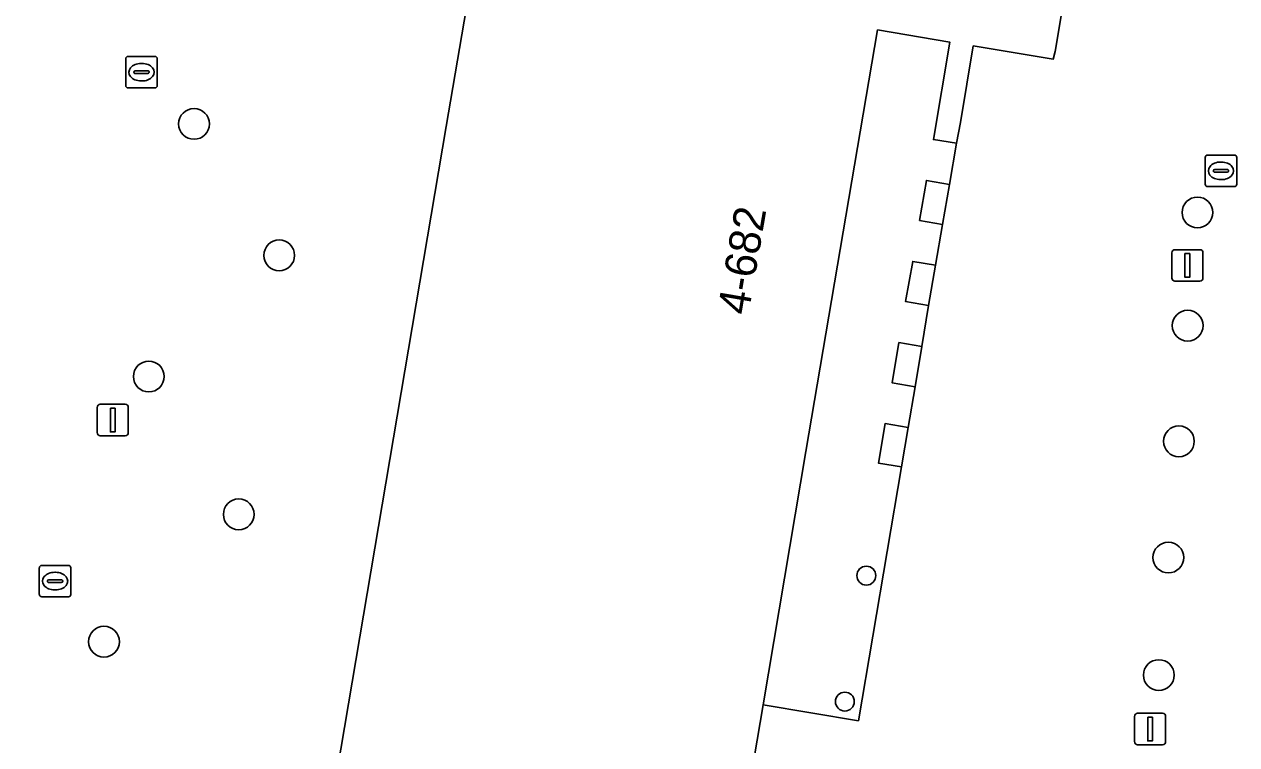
# Model space of a CAD drawing. Extents: x 161258 to 161838, y 380833 to 381727.
# Drawn here: x 161411.27 to 161449.78, y 380983.15 to 381006.05 of the extents above; entities that cross this region are included whole.
import ezdxf

# ---------------------------------------------------------------- set-up
doc = ezdxf.new("R2010")
doc.units = 0
for name, color, linetype in [('IMGEO_Boom', 7, 'Continuous'), ('IMGEO_Erf', 7, 'Continuous'), ('IMGEO_Kolk', 7, 'Continuous'), ('IMGEO_Lichtmast', 7, 'Continuous'), ('IMGEO_Pand', 7, 'Continuous'), ('IMGEO_Pand_nummerreeks', 7, 'Continuous'), ('IMGEO_Pand_overbouw', 7, 'Continuous')]:
    doc.layers.add(name, color=color, linetype=linetype)

msp = doc.modelspace()

# ---------------------------------------------------------------- linework, layer by layer
at = {"layer": 'IMGEO_Boom'}
for centre in [(161416.661, 381002.88), (161448.534, 381000.066), (161419.366, 380998.703), (161448.225, 380996.469), (161415.223, 380994.852), (161447.945, 380992.793), (161418.081, 380990.471), (161447.611, 380989.099), (161413.8, 380986.425), (161447.307, 380985.364)]:
    msp.add_circle(centre, 0.489, dxfattribs=at)
at = {"layer": 'IMGEO_Erf'}
msp.add_lwpolyline([(161408.328, 380973.621), (161419.413, 380971.739), (161420.011, 380975.246), (161424.673, 381002.799), (161429.081, 381028.658), (161440.253, 381026.759), (161437.41, 381010.081), (161444.625, 381008.855), (161444.015, 381005.179), (161443.954, 381004.94), (161441.41, 381005.361), (161441.008, 381002.927), (161440.881, 381002.266), (161440.145, 381002.382), (161440.67, 381005.478), (161438.373, 381005.868), (161436.092, 380992.474), (161434.734, 380984.423), (161433.514, 380977.179), (161432.521, 380971.424), (161434.023, 380971.148), (161434.118, 380956.967)], dxfattribs=at)
for points in [[(161440.436, 380999.688), (161439.709, 380999.812), (161439.925, 381001.083), (161440.659, 381000.958)], [(161439.994, 380997.106), (161439.265, 380997.233), (161439.488, 380998.512), (161440.217, 380998.388)], [(161439.567, 380994.528), (161438.833, 380994.656), (161439.049, 380995.929), (161439.776, 380995.805)], [(161439.133, 380991.981), (161438.399, 380992.102), (161438.612, 380993.356), (161439.341, 380993.233)]]:
    msp.add_lwpolyline(points, close=True, dxfattribs=at)
for centre, start, end in [((161438.016, 380988.524), 90, 270), ((161438.016, 380988.524), 270, 90), ((161437.334, 380984.521), 90, 270), ((161437.334, 380984.521), 270, 90)]:
    msp.add_arc(centre, 0.3, start, end, dxfattribs=at)
at = {"layer": 'IMGEO_Kolk'}
for p, q in [((161414.492, 381004.098), (161414.492, 381004.95)), ((161414.567, 381005.024), (161415.419, 381005.024)), ((161415.493, 381004.95), (161415.493, 381004.098)), ((161414.751, 381004.518), (161414.751, 381004.53)), ((161414.794, 381004.567), (161415.192, 381004.567)), ((161414.98, 381004.804), (161415.005, 381004.804)), ((161415.235, 381004.53), (161415.235, 381004.518)), ((161415.189, 381004.481), (161414.791, 381004.481)), ((161415.003, 381004.244), (161414.978, 381004.244)), ((161415.419, 381004.024), (161414.567, 381004.024)), ((161448.781, 381000.963), (161448.781, 381001.815)), ((161448.856, 381001.889), (161449.708, 381001.889)), ((161449.782, 381001.815), (161449.782, 381000.963)), ((161449.083, 381001.432), (161449.481, 381001.432)), ((161449.269, 381001.669), (161449.294, 381001.669)), ((161449.04, 381001.383), (161449.04, 381001.395)), ((161449.478, 381001.346), (161449.08, 381001.346)), ((161449.292, 381001.109), (161449.267, 381001.109)), ((161449.524, 381001.395), (161449.524, 381001.383)), ((161449.708, 381000.889), (161448.856, 381000.889)), ((161411.746, 380987.925), (161411.746, 380988.777)), ((161411.821, 380988.851), (161412.673, 380988.851)), ((161412.747, 380988.777), (161412.747, 380987.925)), ((161412.005, 380988.345), (161412.005, 380988.357)), ((161412.048, 380988.394), (161412.446, 380988.394)), ((161412.234, 380988.631), (161412.259, 380988.631)), ((161412.489, 380988.357), (161412.489, 380988.345)), ((161412.443, 380988.308), (161412.045, 380988.308)), ((161412.257, 380988.071), (161412.232, 380988.071)), ((161412.673, 380987.851), (161411.821, 380987.851))]:
    msp.add_line(p, q, dxfattribs=at)
for points in [[(161414.492, 381004.098), (161414.492, 381004.95)], [(161414.567, 381005.024), (161415.419, 381005.024)], [(161415.493, 381004.95), (161415.493, 381004.098)], [(161415.419, 381004.024), (161414.567, 381004.024)], [(161448.781, 381000.963), (161448.781, 381001.815)], [(161448.856, 381001.889), (161449.708, 381001.889)], [(161449.782, 381001.815), (161449.782, 381000.963)], [(161449.708, 381000.889), (161448.856, 381000.889)], [(161411.746, 380987.925), (161411.746, 380988.777)], [(161411.821, 380988.851), (161412.673, 380988.851)], [(161412.747, 380988.777), (161412.747, 380987.925)], [(161412.673, 380987.851), (161411.821, 380987.851)]]:
    msp.add_lwpolyline(points, dxfattribs=at)
for centre, radius, start, end in [((161414.569, 381004.948), 0.0765, 91.552, 178.448), ((161414.569, 381004.948), 0.0765, 91.552, 178.448), ((161415.417, 381004.948), 0.0765, 1.552, 88.448), ((161415.417, 381004.948), 0.0765, 1.552, 88.448), ((161414.791, 381004.527), 0.0403, 85.8775, 175.7526), ((161414.788, 381004.517), 0.0366, 178.938, 274.7102), ((161415.192, 381004.524), 0.043, 264.8664, 352.4533), ((161415.196, 381004.529), 0.0386, 1.7309, 96.639), ((161414.569, 381004.1), 0.0765, 181.552, 268.448), ((161414.569, 381004.1), 0.0765, 181.552, 268.448), ((161415.417, 381004.1), 0.0765, 271.552, 358.448), ((161415.417, 381004.1), 0.0765, 271.552, 358.448), ((161448.858, 381001.813), 0.0765, 91.552, 178.448), ((161448.858, 381001.813), 0.0765, 91.552, 178.448), ((161449.706, 381001.813), 0.0765, 1.552, 88.448), ((161449.706, 381001.813), 0.0765, 1.552, 88.448), ((161449.08, 381001.392), 0.0403, 85.8775, 175.7526), ((161449.485, 381001.394), 0.0386, 1.7309, 96.639), ((161449.077, 381001.382), 0.0366, 178.938, 274.7102), ((161449.481, 381001.389), 0.043, 264.8664, 352.4533), ((161448.858, 381000.965), 0.0765, 181.552, 268.448), ((161448.858, 381000.965), 0.0765, 181.552, 268.448), ((161449.706, 381000.965), 0.0765, 271.552, 358.448), ((161449.706, 381000.965), 0.0765, 271.552, 358.448), ((161411.823, 380988.775), 0.0765, 91.552, 178.448), ((161411.823, 380988.775), 0.0765, 91.552, 178.448), ((161412.671, 380988.775), 0.0765, 1.552, 88.448), ((161412.671, 380988.775), 0.0765, 1.552, 88.448), ((161412.045, 380988.354), 0.0403, 85.8775, 175.7526), ((161412.042, 380988.344), 0.0366, 178.938, 274.7102), ((161412.446, 380988.351), 0.043, 264.8664, 352.4533), ((161412.45, 380988.356), 0.0386, 1.7309, 96.639), ((161411.823, 380987.927), 0.0765, 181.552, 268.448), ((161411.823, 380987.927), 0.0765, 181.552, 268.448), ((161412.671, 380987.927), 0.0765, 271.552, 358.448), ((161412.671, 380987.927), 0.0765, 271.552, 358.448)]:
    msp.add_arc(centre, radius, start, end, dxfattribs=at)
for centre, major_axis, ratio, start_param, end_param in [((161414.979, 381004.524), (-0.387, 0.002), 0.722429, 4.712389, 7.853982), ((161415.004, 381004.524), (-0.39, 0.002), 0.717154, 1.570796, 4.712389), ((161449.268, 381001.389), (-0.387, 0.002), 0.722429, 4.712389, 7.853982), ((161449.293, 381001.389), (-0.39, 0.002), 0.717154, 1.570796, 4.712389), ((161412.233, 380988.351), (-0.387, 0.002), 0.722429, 4.712389, 7.853982), ((161412.258, 380988.351), (-0.39, 0.002), 0.717154, 1.570796, 4.712389)]:
    msp.add_ellipse(centre, major_axis=major_axis, ratio=ratio, start_param=start_param, end_param=end_param, dxfattribs=at)
at = {"layer": 'IMGEO_Lichtmast'}
for p, q in [((161447.718, 380997.982), (161447.718, 380998.782)), ((161447.718, 380998.782), (161447.718, 380997.982)), ((161447.818, 380998.882), (161448.608, 380998.882)), ((161448.608, 380998.882), (161447.818, 380998.882)), ((161448.708, 380998.782), (161448.708, 380997.982)), ((161448.708, 380997.982), (161448.708, 380998.782)), ((161448.608, 380997.882), (161447.818, 380997.882)), ((161447.818, 380997.882), (161448.608, 380997.882)), ((161413.582, 380993.069), (161413.582, 380993.869)), ((161413.582, 380993.869), (161413.582, 380993.069)), ((161413.682, 380993.969), (161414.472, 380993.969)), ((161414.472, 380993.969), (161413.682, 380993.969)), ((161414.572, 380993.869), (161414.572, 380993.069)), ((161414.572, 380993.069), (161414.572, 380993.869)), ((161414.472, 380992.969), (161413.682, 380992.969)), ((161413.682, 380992.969), (161414.472, 380992.969)), ((161446.634, 380984.149), (161447.424, 380984.149)), ((161447.424, 380984.149), (161446.634, 380984.149)), ((161446.534, 380983.249), (161446.534, 380984.049)), ((161446.534, 380984.049), (161446.534, 380983.249)), ((161447.524, 380984.049), (161447.524, 380983.249)), ((161447.524, 380983.249), (161447.524, 380984.049)), ((161447.424, 380983.149), (161446.634, 380983.149)), ((161446.634, 380983.149), (161447.424, 380983.149))]:
    msp.add_line(p, q, dxfattribs=at)
for points in [[(161448.138, 380998.757), (161448.288, 380998.757), (161448.288, 380998.007), (161448.138, 380998.007), (161448.138, 380998.757)], [(161414.002, 380993.844), (161414.152, 380993.844), (161414.152, 380993.094), (161414.002, 380993.094), (161414.002, 380993.844)], [(161446.954, 380984.024), (161447.104, 380984.024), (161447.104, 380983.274), (161446.954, 380983.274), (161446.954, 380984.024)]]:
    msp.add_lwpolyline(points, dxfattribs=at)
for centre, start, end in [((161447.818, 380998.782), 90, 180), ((161447.818, 380998.782), 90, 180), ((161448.608, 380998.782), 0, 90), ((161448.608, 380998.782), 360, 90), ((161447.818, 380997.982), 180, 270), ((161447.818, 380997.982), 180, 270), ((161448.608, 380997.982), 270, 0), ((161448.608, 380997.982), 270, 0), ((161413.682, 380993.869), 90, 180), ((161413.682, 380993.869), 90, 180), ((161414.472, 380993.869), 0, 90), ((161414.472, 380993.869), 360, 90), ((161413.682, 380993.069), 180, 270), ((161413.682, 380993.069), 180, 270), ((161414.472, 380993.069), 270, 0), ((161414.472, 380993.069), 270, 0), ((161446.634, 380984.049), 90, 180), ((161446.634, 380984.049), 90, 180), ((161447.424, 380984.049), 0, 90), ((161447.424, 380984.049), 360, 90), ((161446.634, 380983.249), 180, 270), ((161446.634, 380983.249), 180, 270), ((161447.424, 380983.249), 270, 0), ((161447.424, 380983.249), 270, 0)]:
    msp.add_arc(centre, 0.1, start, end, dxfattribs=at)
at = {"layer": 'IMGEO_Pand'}
msp.add_lwpolyline([(161434.118, 380956.967), (161434.023, 380971.148), (161432.521, 380971.424), (161433.514, 380977.179), (161434.734, 380984.423), (161436.092, 380992.474), (161438.373, 381005.868), (161440.67, 381005.478), (161440.145, 381002.382), (161440.881, 381002.266), (161441.008, 381002.927), (161441.41, 381005.361), (161443.954, 381004.94), (161444.015, 381005.179), (161444.625, 381008.855), (161437.41, 381010.081), (161440.253, 381026.759), (161429.081, 381028.658), (161424.673, 381002.799), (161420.011, 380975.246), (161419.413, 380971.739), (161408.328, 380973.621)], dxfattribs=at)
for points in [[(161440.659, 381000.958), (161439.925, 381001.083), (161439.709, 380999.812), (161440.436, 380999.688)], [(161440.217, 380998.388), (161439.488, 380998.512), (161439.265, 380997.233), (161439.994, 380997.106)], [(161439.776, 380995.805), (161439.049, 380995.929), (161438.833, 380994.656), (161439.567, 380994.528)], [(161439.341, 380993.233), (161438.612, 380993.356), (161438.399, 380992.102), (161439.133, 380991.981)]]:
    msp.add_lwpolyline(points, close=True, dxfattribs=at)
for centre, start, end in [((161438.016, 380988.524), 90, 270), ((161438.016, 380988.524), 270, 90), ((161437.334, 380984.521), 90, 270), ((161437.334, 380984.521), 270, 90)]:
    msp.add_arc(centre, 0.3, start, end, dxfattribs=at)
at = {"layer": 'IMGEO_Pand_overbouw'}
msp.add_lwpolyline([(161437.765, 380983.907), (161439.133, 380991.981), (161438.399, 380992.102), (161438.612, 380993.356), (161439.341, 380993.233), (161439.567, 380994.528), (161438.833, 380994.656), (161439.049, 380995.929), (161439.776, 380995.805), (161439.994, 380997.106), (161439.265, 380997.233), (161439.488, 380998.512), (161440.217, 380998.388), (161440.436, 380999.688), (161439.709, 380999.812), (161439.925, 381001.083), (161440.659, 381000.958), (161440.881, 381002.266), (161440.145, 381002.382), (161440.67, 381005.478), (161438.373, 381005.868), (161436.092, 380992.474), (161434.734, 380984.423)], close=True, dxfattribs=at)

# ---------------------------------------------------------------- texts
at = {"layer": 'IMGEO_Pand_nummerreeks'}
msp.add_text('4-682', height=1, rotation=80.3344, dxfattribs=at).set_placement((161434.269, 380996.779))

doc.saveas('drawing.dxf')
